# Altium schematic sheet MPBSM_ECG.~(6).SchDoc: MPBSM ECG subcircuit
size 431 x 279 mm; Date: Not shown in title block; ApprovedBy: Not shown in title block; CheckedBy: Not shown in title block; Author: Not shown in title block; CompanyName: Not shown in title block; Engineer: Not shown in title block; Organization: Not shown in title block; Address1: Not shown in title block; Address2: Not shown in title block; Address3: Not shown in title block; Address4: Not shown in title block; DocumentNumber: 8; Revision: Use project parameter SCH_Rev; SheetNumber: 7; SheetTotal: 12; PageSetup: Record=PageOptions¦CenterHorizontal=True¦CenterVertical=True¦PrintScale=1.00¦XCorrection=1.00¦YCorrection=1.00¦PrintKind=0¦BorderSize=5000000¦LeftOffset=0¦BottomOffset=0¦Orientation=2¦PaperLength=1000¦PaperWidth=1000¦Scale=100¦PaperSource=15¦PrintQuality=600¦MediaType=1¦DitherType=10¦PaperKind=Letter¦PrintScaleMode=1
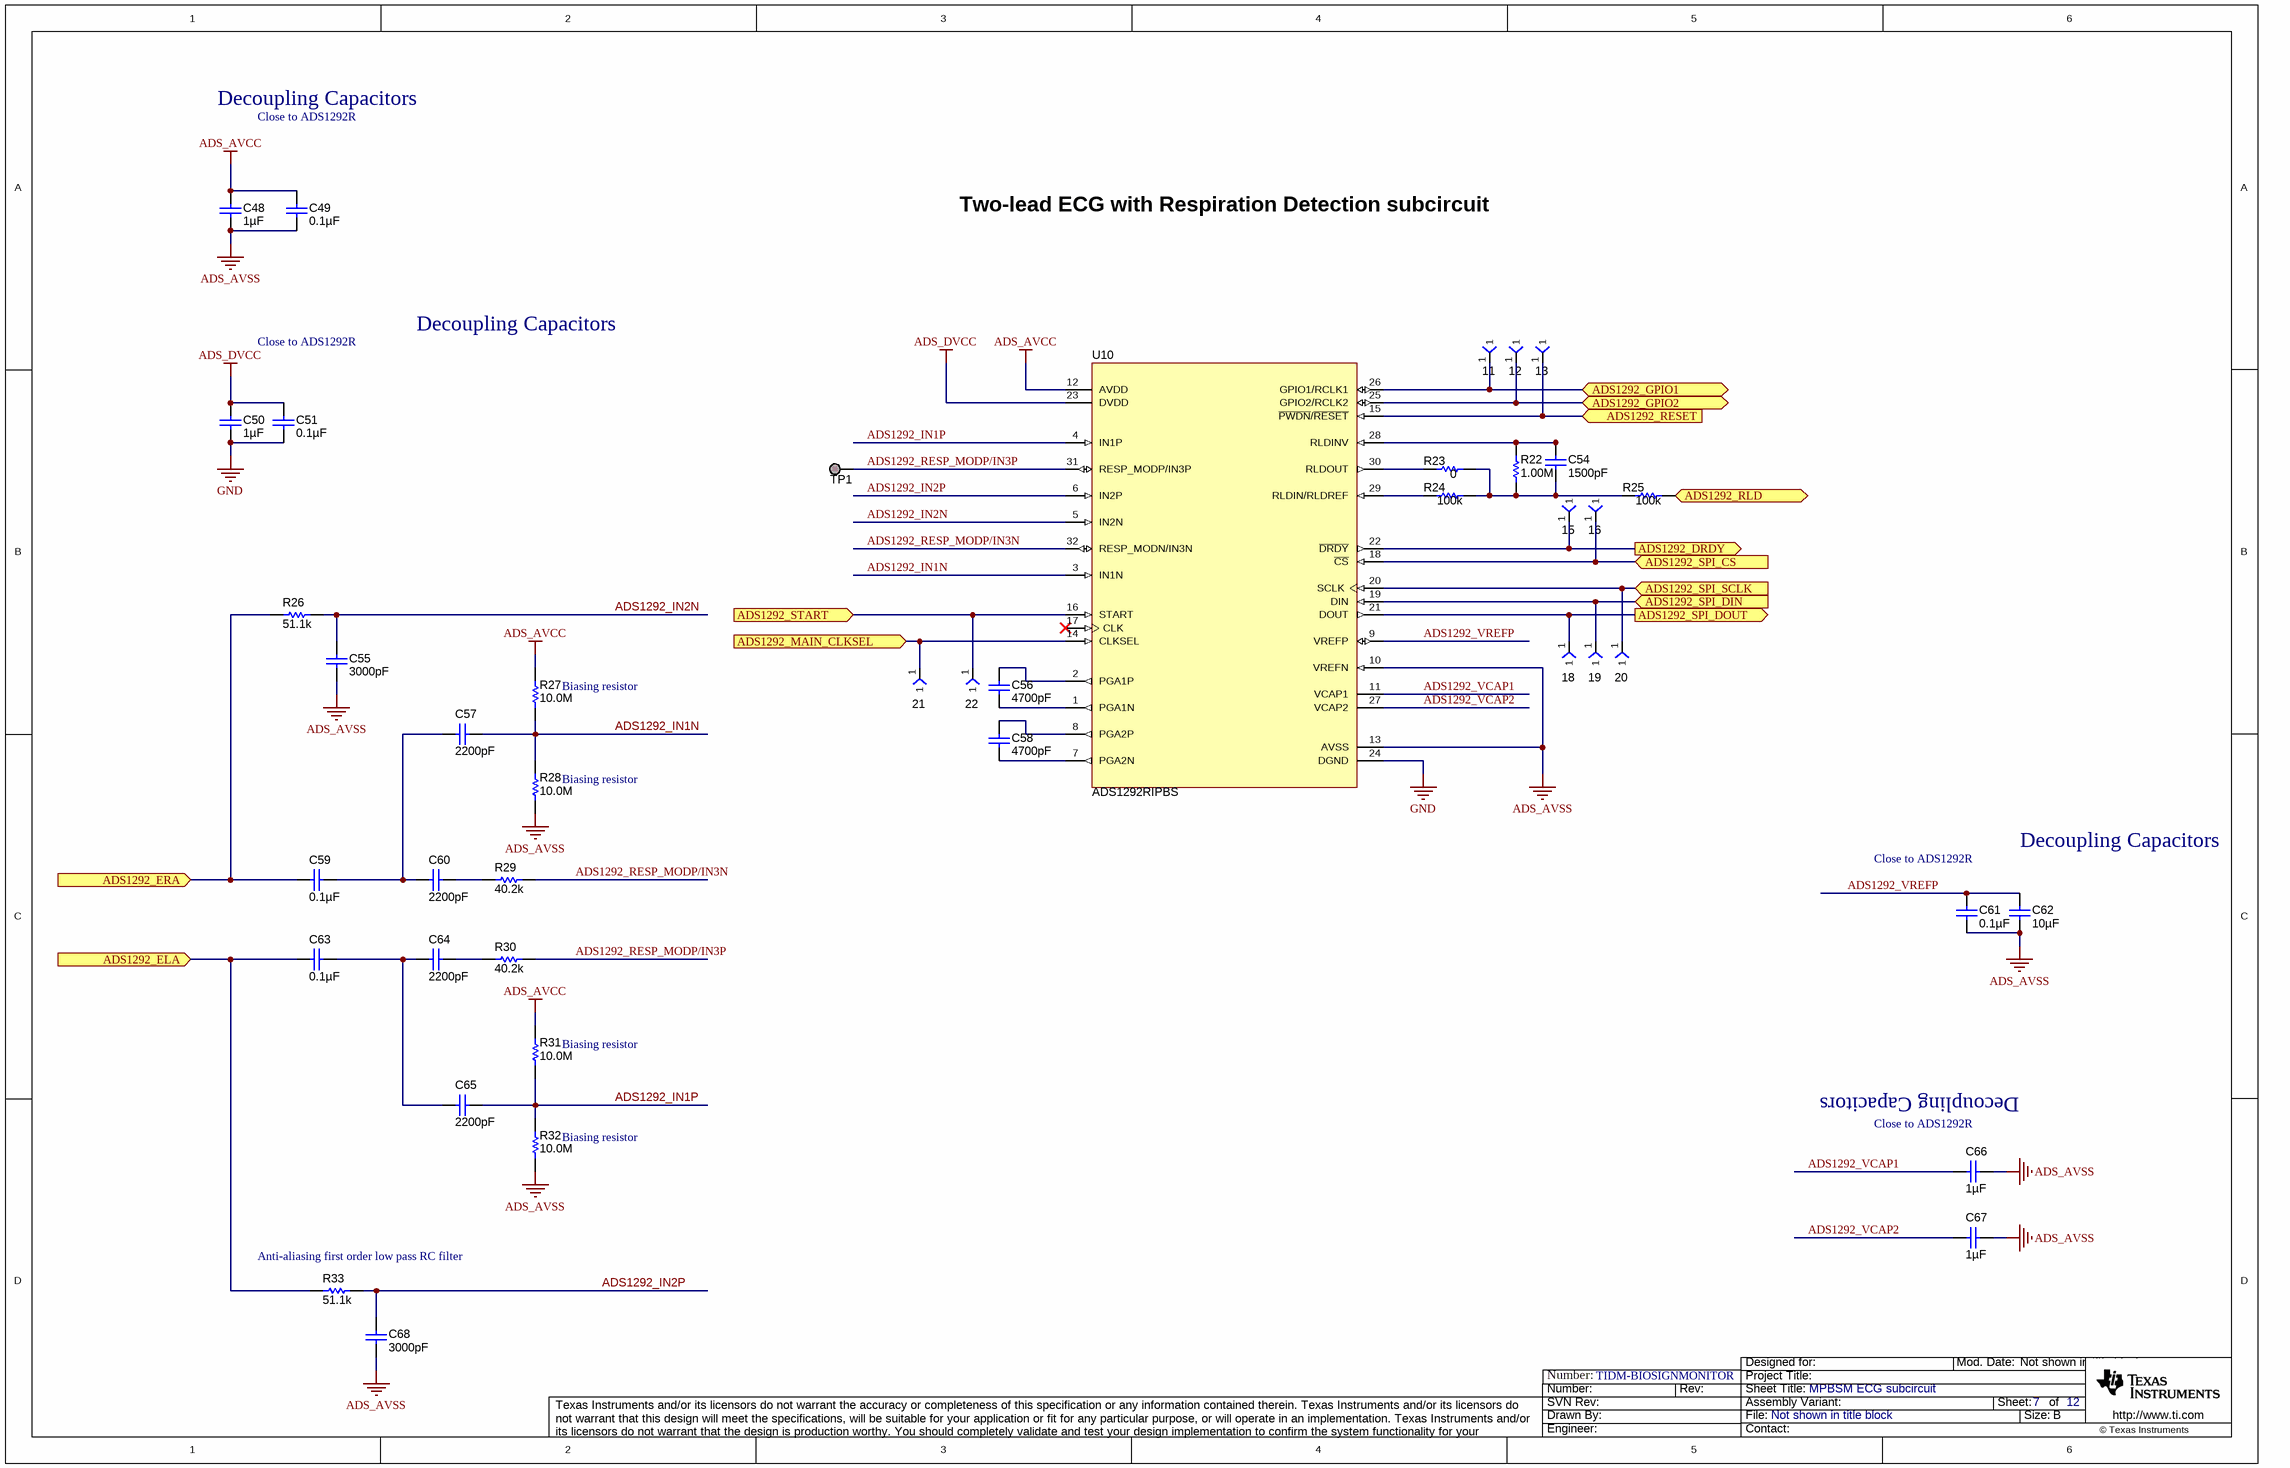
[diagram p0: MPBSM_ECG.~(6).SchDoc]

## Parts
11  TP-025-SMT  [TP_25MIL-SMT]  (value not drawn)
12  TP-025-SMT  [TP_25MIL-SMT]  (value not drawn)
13  TP-025-SMT  [TP_25MIL-SMT]  (value not drawn)
15  TP-025-SMT  [TP_25MIL-SMT]  (value not drawn)
16  TP-025-SMT  [TP_25MIL-SMT]  (value not drawn)
18  TP-025-SMT  [TP_25MIL-SMT]  (value not drawn)
19  TP-025-SMT  [TP_25MIL-SMT]  (value not drawn)
20  TP-025-SMT  [TP_25MIL-SMT]  (value not drawn)
21  TP-025-SMT  [TP_25MIL-SMT]  (value not drawn)
22  TP-025-SMT  [TP_25MIL-SMT]  (value not drawn)
C48  ValueDisplayed: 1µF  [0402]  (hidden comment: C1005X5R1C105K050BC)
C49  ValueDisplayed: 0.1µF  [0402]  (hidden comment: C1005X5R1A104K)
C50  ValueDisplayed: 1µF  [0402]  (hidden comment: C1005X5R1C105K050BC)
C51  ValueDisplayed: 0.1µF  [0402]  (hidden comment: C1005X5R1A104K)
C54  ValueDisplayed: 1500pF  [0603]  (hidden comment: C0603C152K5RACTU)
C55  ValueDisplayed: 3000pF  [0603]  (hidden comment: GRM1885C1H302JA01D)
C56  ValueDisplayed: 4700pF  [0402]  (hidden comment: GRM155R61A472KA01D)
C57  ValueDisplayed: 2200pF  [0402]  (hidden comment: C1005X8R1H222K)
C58  ValueDisplayed: 4700pF  [0402]  (hidden comment: GRM155R61A472KA01D)
C59  ValueDisplayed: 0.1µF  [0402]  (hidden comment: C1005X5R1A104K)
C60  ValueDisplayed: 2200pF  [0402]  (hidden comment: C1005X8R1H222K)
C61  ValueDisplayed: 0.1µF  [0402]  (hidden comment: C1005X5R1A104K)
C62  ValueDisplayed: 10µF  [0603]  (hidden comment: C1608X5R0J106M)
C63  ValueDisplayed: 0.1µF  [0402]  (hidden comment: C1005X5R1A104K)
C64  ValueDisplayed: 2200pF  [0402]  (hidden comment: C1005X8R1H222K)
C65  ValueDisplayed: 2200pF  [0402]  (hidden comment: C1005X8R1H222K)
C66  ValueDisplayed: 1µF  [0402]  (hidden comment: C1005X5R1C105K050BC)
C67  ValueDisplayed: 1µF  [0402]  (hidden comment: C1005X5R1C105K050BC)
C68  ValueDisplayed: 3000pF  [0603]  (hidden comment: GRM1885C1H302JA01D)
R22  ValueDisplayed: 1.00M  [0402]  (hidden comment: ERJ-2RKF1004X)
R23  ValueDisplayed: 0  [0402]  (hidden comment: ERJ-2GE0R00X)
R24  ValueDisplayed: 100k  [0402]  (hidden comment: ERJ-2RKF1003X)
R25  ValueDisplayed: 100k  [0402]  (hidden comment: ERJ-2RKF1003X)
R26  ValueDisplayed: 51.1k  [0402]  (hidden comment: CRCW040251K1FKED)
R27  ValueDisplayed: 10.0M  [0402]  (hidden comment: CRCW040210M0FKED)
R28  ValueDisplayed: 10.0M  [0402]  (hidden comment: CRCW040210M0FKED)
R29  ValueDisplayed: 40.2k  [0402]  (hidden comment: CRCW040240K2FKED)
R30  ValueDisplayed: 40.2k  [0402]  (hidden comment: CRCW040240K2FKED)
R31  ValueDisplayed: 10.0M  [0402]  (hidden comment: CRCW040210M0FKED)
R32  ValueDisplayed: 10.0M  [0402]  (hidden comment: CRCW040210M0FKED)
R33  ValueDisplayed: 51.1k  [0402]  (hidden comment: CRCW040251K1FKED)
TP1  Pogo Pad  [PogoPad]  (value not drawn)  (no BOM)
U10  ADS1292RIPBS  [PBS0032A_N]

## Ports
ADS1292_DRDY (out), ADS1292_ELA (in), ADS1292_ERA (in), ADS1292_GPIO1 (bidir), ADS1292_GPIO2 (bidir), ADS1292_MAIN_CLKSEL (in), ADS1292_RESET (in), ADS1292_RLD (out), ADS1292_SPI_CS (in), ADS1292_SPI_DIN (in), ADS1292_SPI_DOUT (out), ADS1292_SPI_SCLK (in), ADS1292_START (in)

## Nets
ADS_AVCC: C48.1 C49.1 R27.2 R31.2 U10.12(AVDD)
ADS_AVSS: C48.2 C49.2 C55.2 C61.2 C62.2 C66.2 C67.2 C68.2 R28.1 R32.1 U10.10(VREFN) U10.13(AVSS)
ADS_DVCC: C50.1 C51.1 U10.23(DVDD)
GND: C50.2 C51.2 U10.24(DGND)
ADS1292_DRDY: 15.1 U10.22(~{DRDY}) ; port ADS1292_DRDY
ADS1292_ELA: C63.1 R33.1 ; port ADS1292_ELA
ADS1292_ERA: C59.1 R26.1 ; port ADS1292_ERA
ADS1292_GPIO1: 11.1 U10.26(GPIO1/RCLK1) ; port ADS1292_GPIO1
ADS1292_GPIO2: 12.1 U10.25(GPIO2/RCLK2) ; port ADS1292_GPIO2
ADS1292_IN1N: C57.1 R27.1 R28.2 U10.3(IN1N)
ADS1292_IN1P: C65.1 R31.1 R32.2 U10.4(IN1P)
ADS1292_IN2N: C55.1 R26.2 U10.5(IN2N)
ADS1292_IN2P: C68.1 R33.2 U10.6(IN2P)
ADS1292_MAIN_CLKSEL: 21.1 U10.14(CLKSEL) ; port ADS1292_MAIN_CLKSEL
ADS1292_RESET: 13.1 U10.15(~{PWDN}/~{RESET}) ; port ADS1292_RESET
ADS1292_RESP_MODP/IN3N: R29.2 U10.32(RESP_MODN/IN3N)
ADS1292_RESP_MODP/IN3P: R30.2 TP1.1 U10.31(RESP_MODP/IN3P)
ADS1292_RLD: R25.2 ; port ADS1292_RLD
ADS1292_SPI_CS: 16.1 U10.18(~{CS}) ; port ADS1292_SPI_CS
ADS1292_SPI_DIN: 19.1 U10.19(DIN) ; port ADS1292_SPI_DIN
ADS1292_SPI_DOUT: 18.1 U10.21(DOUT) ; port ADS1292_SPI_DOUT
ADS1292_SPI_SCLK: 20.1 U10.20(SCLK) ; port ADS1292_SPI_SCLK
ADS1292_START: 22.1 U10.16(START) ; port ADS1292_START
ADS1292_VCAP1: C66.1 U10.11(VCAP1)
ADS1292_VCAP2: C67.1 U10.27(VCAP2)
ADS1292_VREFP: C61.1 C62.1 U10.9(VREFP)
NetC54_1: C54.1 R22.2 R23.2 R24.2 R25.1
NetC54_2: C54.2 R22.1 U10.28(RLDINV)
NetC56_1: C56.1 U10.2(PGA1P)
NetC56_2: C56.2 U10.1(PGA1N)
NetC57_2: C57.2 C59.2 C60.2
NetC58_1: C58.1 U10.8(PGA2P)
NetC58_2: C58.2 U10.7(PGA2N)
NetC60_1: C60.1 R29.1
NetC63_2: C63.2 C64.2 C65.2
NetC64_1: C64.1 R30.1
NetR23_1: R23.1 U10.30(RLDOUT)
NetR24_1: R24.1 U10.29(RLDIN/RLDREF)

Not connected (* = marked no-connect by the designer): U10 17(CLK)*

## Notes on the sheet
- Decoupling Capacitors
- Close to ADS1292R
- Two-lead ECG with Respiration Detection subcircuit
- (near R27) Biasing resistor
- (near R28) Biasing resistor
- (near R31) Biasing resistor
- (near R32) Biasing resistor
- (near C66) Close to ADS1292R
- (near R33) Anti-aliasing first order low pass RC filter
- Number:
- TIDM-BIOSIGNMONITOR

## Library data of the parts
11-13 15 16 18-22 = TP-025-SMT: Test Point, O.025"; Manufacturer: STD; Value: STD
C48 C50 C66 C67 = C1005X5R1C105K050BC: CAP, CERM, 1 µF, 16 V, +/- 10%, X5R, 0402; Manufacturer: TDK; Polarized: N; CompType: Capacitor; Value: 1uF; U/M: EA; Cap_F: 0.000001; Tolerance_%: 10; Value1: Unknown; VDC_V: 16; Value2: 16V; TaMin_C: -55; TaMax_C: 85
C49 C51 C59 C61 C63 = C1005X5R1A104K: CAP, CERM, 0.1 µF, 10 V, +/- 10%, X5R, 0402; Manufacturer: TDK; Polarized: N; CompType: Capacitor; Value: 0.1uF; U/M: EA; Cap_F: 0.0000001; Tolerance_%: 10; ESR_ohm: 0.0186; Value1: 0.0186 ohm; Value2: 10V; TaMin_C: -55; TaMax_C: 85
C54 = C0603C152K5RACTU: CAP, CERM, 1500 pF, 50 V, +/- 10%, X7R, 0603; Manufacturer: Kemet; Polarized: N; CompType: Capacitor; Value: 1500pF; U/M: EA; Cap_F: 0.0000000015; Tolerance_%: 10; Value1: Unknown; VDC_V: 50; Value2: 50V; TaMin_C: -55; TaMax_C: 125
C55 C68 = GRM1885C1H302JA01D: CAP, CERM, 3000 pF, 50 V, +/- 5%, C0G/NP0, 0603; Manufacturer: MuRata; Polarized: N; CompType: Capacitor; Value: 3000pF; U/M: EA; Cap_F: 0.000000003; Tolerance_%: 5; Value1: Unknown; VDC_V: 50; Value2: 50V; TaMin_C: -55; TaMax_C: 125
C56 C58 = GRM155R61A472KA01D: CAP, CERM, 4700 pF, 10 V, +/- 10%, X5R, 0402; Manufacturer: MuRata; Polarized: N; CompType: Capacitor; Value: 4700pF; U/M: EA; Cap_F: 0.0000000047; Tolerance_%: 10; Value1: Unknown; Value2: 10V; TaMin_C: -55; TaMax_C: 85
C57 C60 C64 C65 = C1005X8R1H222K: CAP, CERM, 2200 pF, 50 V, +/- 10%, X8R, 0402; Manufacturer: TDK; Polarized: N; CompType: Capacitor; Value: 2200pF; U/M: EA; Cap_F: 0.0000000022; Tolerance_%: 10; ESR_ohm: 0.1736; Value1: 0.1736 ohm; VDC_V: 50; Value2: 50V; TaMin_C: -55; TaMax_C: 150
C62 = C1608X5R0J106M: CAP, CERM, 10 µF, 6.3 V, +/- 20%, X5R, 0603; Manufacturer: TDK; Polarized: N; CompType: Capacitor; Value: 10uF; U/M: EA; Cap_F: 0.00001; Tolerance_%: 20; ESR_ohm: 0.005; Value1: 0.005 ohm; VDC_V: 6.3; Value2: 6.3V; IRMS_A: 1.9; TaMin_C: -25; TaMax_C: 85
R22 = ERJ-2RKF1004X: RES, 1.00 M, 1%, 0.1 W, 0402; Manufacturer: Panasonic; CompType: Resistor; Value: 1.00Meg; Res_ohm: 1000000; Value_Code: 1M00; Tolerance_%: 1; Power_W: 0.1; Value2: 0.1W; VDC_V: 50; TempCo: 100 ppm/C; EIA_Code: E96; U/M: EA
R23 = ERJ-2GE0R00X: RES, 0, 5%, 0.063 W, 0402; Manufacturer: Panasonic; CompType: Resistor; Value: 0; Value_Code: 0000; Tolerance_%: 5; Power_W: 0.063; Value2: 0.063W; VDC_V: 50; TempCo: 600 ppm/C; EIA_Code: E24; U/M: EA
R24 R25 = ERJ-2RKF1003X: RES, 100 k, 1%, 0.1 W, 0402; Manufacturer: Panasonic; CompType: Resistor; Value: 100k; Res_ohm: 100000; Tolerance_%: 1; Power_W: 0.1; Value2: 0.1W; VDC_V: 50; TempCo: 100 ppm/C; EIA_Code: E96; U/M: EA
R26 R33 = CRCW040251K1FKED: RES, 51.1 k, 1%, 0.063 W, 0402; Manufacturer: Vishay-Dale; CompType: Resistor; Value: 51.1k; Res_ohm: 51100; Value_Code: 51k1; Tolerance_%: 1; Power_W: 0.063; Value2: 0.063W; VDC_V: 50; TempCo: 100 ppm/C; EIA_Code: E96; U/M: EA
R27 R28 R31 R32 = CRCW040210M0FKED: RES, 10.0 M, 1%, 0.063 W, 0402; Manufacturer: Vishay-Dale; CompType: Resistor; Value: 10.0Meg; Res_ohm: 10000000; Value_Code: 10M0; Tolerance_%: 1; Power_W: 0.063; Value2: 0.063W; VDC_V: 50; TempCo: 100 ppm/C; EIA_Code: E96; U/M: EA
R29 R30 = CRCW040240K2FKED: RES, 40.2 k, 1%, 0.063 W, 0402; Manufacturer: Vishay-Dale; CompType: Resistor; Value: 40.2k; Res_ohm: 40200; Value_Code: 40k2; Tolerance_%: 1; Power_W: 0.063; Value2: 0.063W; VDC_V: 50; TempCo: 100 ppm/C; EIA_Code: E96; U/M: EA
TP1 = PogoPad: Pad for Pogo Pin Connector; SymbolCreator: codlsc
U10 = ADS1292RIPBS: Low-Power, 2-Channel, 24-Bit Analog Front-End for Biopotential Measurement, PBS0032A; Alternate Manufacturer: None; Manufacturer: Texas Instruments; SymbolCreator: Altium; CompType: IC; U/M: EA; SupplyCurrent: 740µW; SupplyVoltageAnalog: 2.7 V ~ 5.25 V; SupplyVoltageAnalogMax_V: 5.25 V; SupplyVoltageAnalogMin_V: 2.7 V; TaMax_C: + 85 °C; TaMin_C: -40 °C; Value: Mixed-Signal; Value1: Not Applicable; SupplyVoltageDigitalMax_V: 3.6 V; SupplyVoltageDigital: 1.7 V ~ 3.6 V; SupplyVoltageDigitalMin_V: 1.7 V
